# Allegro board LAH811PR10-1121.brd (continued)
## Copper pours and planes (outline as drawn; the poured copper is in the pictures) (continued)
PD_L_DRAIN2 on BOTTOM (solid shape): 32.01,35.22 32.01,35.03 31.97,34.99 30.85,34.99 30.75,34.88 30.75,33.78 30.85,33.68 31.97,33.68 32.02,33.63 32.02,33.44 31.96,33.37 28.5,33.37 28.36,33.23 28.36,32.16 28.31,32.11 28.16,32.11 28.08,32.18 28.08,33.28 28.16,33.36 28.16,35.12 30.68,35.12 30.82,35.27 31.96,35.27
PD_L_DRAIN2 on IN2 (solid shape): 30.75,35.1 30.75,33.37 28.16,33.37 28.16,35.12 30.73,35.12
PD_L_DRAIN2 on IN3 (solid shape): 30.75,33.37 28.16,33.37 28.16,35.12 30.75,35.12
PD_L_DRAIN2 on IN1: 28.16,33.37 28.16,35.12 30.75,35.12 30.75,33.37
PD_R_DRAIN1 on TOP (solid shape): 266.42,37.6 266.42,37.36 266.39,37.33 265.35,37.33 265.14,37.12 265.14,36.13 265.27,36 266.23,36 266.28,35.94 266.28,35.77 266.22,35.71 265.32,35.71 265.32,35.71 262.88,35.71 262.74,35.57 262.74,34.49 262.69,34.44 262.47,34.44 262.44,34.48 262.44,35.59 262.6,35.74 262.6,37.46 265.15,37.46 265.31,37.62 266.4,37.62
PD_R_DRAIN1 on BOTTOM (solid shape): 265.14,35.87 265.05,35.78 262.7,35.78 262.6,35.88 262.6,37.46 262.61,37.46 265.14,37.46
PD_R_DRAIN1 on IN1 (solid shape): 265.14,35.77 265.08,35.71 262.63,35.71 262.6,35.74 262.6,37.46 262.61,37.46 265.14,37.46
PD_R_DRAIN1 on IN2 (solid shape): 265.14,35.87 265.05,35.78 262.7,35.78 262.6,35.88 262.6,37.46 262.61,37.46 265.14,37.46
PD_R_DRAIN1 on IN3 (solid shape): 265.14,37.4 265.14,35.79 265.06,35.71 262.7,35.71 262.6,35.81 262.6,37.38 262.68,37.46 265.07,37.46
PD_R_DRAIN2 on TOP (solid shape): 259.69,37.46 262.24,37.46 262.24,35.68 262.32,35.6 262.32,34.5 262.24,34.42 262.1,34.42 262.04,34.48 262.04,35.58 261.91,35.71 259.59,35.71 259.58,35.69 258.45,35.69 258.38,35.76 258.38,35.95 258.43,36 259.48,36 259.54,36.06 259.54,37.26 259.5,37.31 258.44,37.31 258.4,37.35 258.4,37.53 258.45,37.58 259.56,37.58
PD_R_DRAIN2 on BOTTOM (solid shape): 262.24,35.89 262.13,35.78 260.5,35.78 260.5,36.24 259.66,36.24 259.66,37.46 262.24,37.46
PD_R_DRAIN2 on IN1 (solid shape): 262.24,35.76 262.19,35.71 259.78,35.71 259.65,35.84 259.65,37.46 259.66,37.46 262.24,37.46
PD_R_DRAIN2 on IN2 (solid shape): 262.24,35.89 262.13,35.78 259.78,35.78 259.66,35.91 259.66,37.46 262.24,37.46
PD_R_DRAIN2 on IN3 (solid shape): 262.24,37.44 262.24,35.81 262.14,35.71 260.38,35.71 260.38,36.05 259.66,36.77 259.66,37.42 259.7,37.46 262.22,37.46
RING2 on TOP (solid shape): 261.15,66.64 261.15,65.83 260.93,65.6 260.93,64.05 260.87,64 260.77,64 260.7,64.07 260.7,66.62 260.82,66.75 261.05,66.75
RING2 on BOTTOM (solid shape): 261.71,67.76 261.71,66.39 261,65.68 260.82,65.68 260.7,65.81 260.7,66.61 260.7,66.61 260.7,67.76 260.95,68.01 260.95,68.01 261.46,68.01
RING2 on IN3: 262.47,68.46 261.52,68.46 260.69,67.63 260.69,65.79 260.82,65.66 261.52,65.66 261.71,65.85 261.71,67.12 262.03,67.44 262.35,67.44 262.47,67.57
RING2 on IN3: 269.84,64.2 270.85,64.2 272.06,63 272.06,61.78 271.77,61.49 271.35,61.49 271.04,61.79 271.04,62.43 270.28,63.19 269.84,63.19
SLEEVE on TOP (solid shape): 260.54,67.39 260.54,64.08 260.47,64 260.36,64 260.29,64.07 260.29,65.6 260.04,65.86 260.04,67.38 260.1,67.44 260.49,67.44
SLEEVE on BOTTOM: 275.87,67.95 275.87,68.71 275.62,68.97 274.66,68.97 274.54,68.84 274.54,68.2 274.85,67.89 275.81,67.89
SLEEVE on IN2: 259.04,66.74 259.04,64.65 259.49,64.2 273.84,64.2 276.06,66.43 276.06,68.46 275.81,68.71 274.66,68.71 274.35,68.39 274.35,66.3 273.27,65.22 260.95,65.22 260.57,65.6 260.57,66.74 260.44,66.87 259.17,66.87
SLEEVE_CONN on BOTTOM: 274.55,67.75 274.73,67.57 276.61,67.57 276.65,67.53 276.65,67.2 276.38,66.93 276.38,65.82 276.11,65.55 272.2,65.55 272.12,65.63 272.12,67.56 272.31,67.75
SN_1.1V_MEM on BOTTOM (solid shape): 100.67,21.53 100.67,20.64 101.06,20.26 101.06,19.63 100.93,19.5 99.53,19.5 99.4,19.63 99.4,21.53 99.53,21.66 100.55,21.66
SN_3V on BOTTOM: 206.54,22.01 206.67,22.01 208.07,20.62 208.07,20.49 207.18,19.6 206.92,19.6 205.91,20.62 205.91,21.38
SNUB_CHG1 on BOTTOM (solid shape): 82.78,9.05 82.78,8.4 82.57,8.2 79.34,8.2 79.21,8.32 79.21,8.83 79.34,8.96 79.85,8.96 80.23,9.34 82.49,9.34
SNUB_CHG2 on BOTTOM (solid shape): 92.93,13.91 92.93,13.15 93.05,13.02 93.82,13.02 93.94,12.9 93.94,12.01 93.82,11.88 92.29,11.88 92.17,12.01 92.17,13.91 92.29,14.04 92.8,14.04
SPK_L+ on TOP: 19.65,29.15 19.65,30.27 17.41,32.5 17.41,32.68 17.57,32.83 20.66,32.83 20.92,32.58 20.92,30.17 23.43,27.65 23.43,27.09 23.33,26.99 21.81,26.99
SPK_L+ on BOTTOM: 17.21,32.07 17.08,32.2 17.08,32.71 17.21,32.83 19.75,32.83 19.88,32.71 19.88,32.2 19.75,32.07
SPK_L+_R on TOP (solid shape): 24.47,27.78 24.47,25.93 24.32,25.77 24.32,24.05 24.27,24 24.09,24 24.02,24.07 24.02,25.72 24,25.74 24,25.79 23.66,26.13 23.66,27.78 23.79,27.91 24.35,27.91
SPK_L- on TOP: 22.44,32.96 22.44,30.8 22.95,30.29 25.62,30.29 26.25,29.66 26.25,28.08 26.1,27.93 25.57,27.93 24.47,29.02 22.57,29.02 21.24,30.36 21.24,32.64 20.79,33.09 17.62,33.09 17.26,33.44 17.26,34.16 17.34,34.23 21.17,34.23
SPK_L- on BOTTOM: 17.21,33.09 17.08,33.22 17.08,33.98 17.21,34.1 18.1,34.1 18.48,33.72 19.75,33.72 19.88,33.6 19.88,33.22 19.75,33.09
SPK_L-_R on TOP (solid shape): 26.38,27.45 26.38,25.94 26.76,25.56 26.76,24.95 26.38,24.57 26.38,24.15 26.2,23.97 24.91,23.97 24.83,24.05 24.83,24.22 24.93,24.33 25.31,24.33 25.49,24.5 25.49,26.84 25.36,26.97 25.36,27.65 25.44,27.73 26.1,27.73
SPK_R+ on TOP: 265.77,29.66 265.77,29.28 265.9,29.15 267.81,29.15 267.93,29.28 267.93,30.17 267.92,30.18 267.92,30.69 267.73,30.88 267.11,30.88 266.99,30.77 266.99,30.37 266.42,29.79 266.29,29.79 266.28,29.79 265.9,29.79
SPK_R+ on BOTTOM: 271.24,33.6 271.36,33.47 271.36,32.71 271.24,32.58 268.06,32.58 267.93,32.71 267.93,33.47 268.06,33.6
SPK_R+ on IN3: 269.08,33.47 269.2,33.34 269.2,32.83 269.08,32.71 268.06,32.71 267.58,32.23 267.58,29.39 267.47,29.28 266.61,29.28 266.42,29.46 266.42,32.21 267.68,33.47
SPK_R+_R on TOP (solid shape): 269.2,31.69 270.6,31.69 270.68,31.61 270.68,31.46 270.61,31.39 268.85,31.39 268.77,31.31 268.06,31.31 267.92,31.18 267.06,31.18 266.93,31.31 266.93,31.83 267.04,31.95 268.95,31.95
SPK_R- on TOP: 269.84,39.06 269.97,38.93 270.22,38.93 270.35,38.8 270.35,38.07 270.2,37.92 268.9,37.92 268.82,38 268.82,39.95 268.85,39.97 268.85,40.13 269.12,40.4 269.7,40.4 269.84,40.26
SPK_R- on BOTTOM: 268.03,31.46 267.93,31.56 267.93,32.2 268.06,32.33 271.24,32.33 271.36,32.2 271.36,31.69 271.13,31.46
SPK_R- on IN3: 270.09,39.69 270.73,39.06 270.73,32.07 270.22,31.56 268.06,31.56 267.93,31.69 267.93,32.33 268.06,32.45 269.2,32.45 269.58,32.83 269.58,38.42 268.82,39.18 268.82,39.44 269.08,39.69
SPK_R-_R on TOP (solid shape): 270.19,37.51 270.19,35.93 270.41,35.72 270.41,34.17 270.85,33.73 270.85,32.21 270.82,32.17 270.6,32.17 270.52,32.25 270.52,32.91 269.76,33.67 269.76,35.07 269.18,35.65 269.18,35.93 268.92,36.19 268.92,37.38 269.03,37.48 269.03,37.49 269.13,37.59 270.12,37.59
N30252391 on BOTTOM (solid shape): 33.92,13.73 33.92,13.58 32.48,12.13 32.35,12.13 31.97,12.51 31.97,13.02 33.24,14.29 33.36,14.29
N30258320 on BOTTOM (solid shape): 39.72,7.48 39.72,6.86 39.57,6.71 37.41,6.71 37.35,6.77 37.35,7.32 37.41,7.38 38.2,7.38 38.46,7.64 39.55,7.64
N30277718 on TOP (solid shape): 39.71,3.5 39.71,1.59 39.59,1.47 37.17,1.47 37.05,1.59 37.05,3.5 37.17,3.62 39.59,3.62
N52032474 on TOP (solid shape): 202.21,63.87 202.21,63.75 201.39,62.92 201,62.92 200.38,63.55 200.38,63.82 201.19,64.64 201.45,64.64
N52032474 on BOTTOM (solid shape): 204.61,65.09 204.61,64.13 204.43,63.95 203.04,63.95 202.66,63.57 202.2,63.57 200.6,61.97 200.11,61.97 199.72,61.59 199.62,61.59 199.47,61.73 199.47,61.85 200.14,62.52 200.14,63.59 201.28,64.74 201.44,64.74 201.89,65.19 204.51,65.19
N52416800 on TOP: 33.24,2.38 31.59,2.38 31.43,2.23 31.43,1.53 31.51,1.45 33.26,1.45 33.3,1.49 33.3,2.32
N52752182 on BOTTOM (solid shape): 196.95,61.26 196.95,61.19 195.62,59.86 195.56,59.86 195.05,60.37 195.05,60.43 196.38,61.77 196.44,61.77
N52761358 on BOTTOM (solid shape): 189.49,68.59 189.8,68.59 190.25,68.14 190.25,68.01 189.68,67.44 189.55,67.44 188.53,68.46 188.53,68.52 188.98,68.97 189.1,68.97
N52765760 on BOTTOM (solid shape): 104.74,30.17 104.74,28.52 104.61,28.39 102.71,28.39 102.58,28.52 102.58,30.14 102.68,30.24 104.67,30.24
N52768296 on BOTTOM (solid shape): 103.72,39.5 103.72,38.55 103.91,38.36 104.87,38.36 104.93,38.3 104.93,37.66 104.87,37.6 102.71,37.6 102.58,37.72 102.58,39.5 102.64,39.57 103.66,39.57
N52924590 on TOP (solid shape): 203.54,49.98 203.54,48.07 203.29,47.82 202.02,47.82 201.89,47.95 201.89,49.34 202.66,50.11 203.42,50.11
N52924590 on BOTTOM (solid shape): 203.48,50.17 203.48,46.49 203.04,46.04 203.04,45.66 202.97,45.6 202.72,45.6 202.66,45.66 202.66,47.12 201.48,48.29 201.48,48.83 201.89,49.24 201.89,50.23 201.96,50.3 203.35,50.3
N52928923 on BOTTOM (solid shape): 192.5,52.65 192.5,50.93 192.43,50.87 191.54,50.87 191.48,50.93 191.48,51.38 190.97,51.88 190.97,52.65 191.03,52.71 192.43,52.71
N52929663 on TOP (solid shape): 204.94,42.11 204.94,41.72 204.81,41.6 202.91,41.6 202.78,41.72 202.78,42.11 202.91,42.23 204.81,42.23
N53177904 on BOTTOM (solid shape): 195.42,63.06 195.42,62.81 194.91,62.3 194.78,62.3 193.64,63.44 193.64,63.57 194.15,64.08 194.4,64.08
N53201443 on BOTTOM: 29.68,13.66 29.55,13.78 29.55,14.29 29.17,14.67 26.76,14.67 26.63,14.8 26.63,15.18 26.76,15.31 28.28,15.31 28.67,15.69 30.19,15.69 30.32,15.82 30.32,16.71 29.94,17.09 29.94,21.79 30.19,22.04 31.59,22.04 32.09,22.55 35.4,22.55 35.47,22.47 35.47,21.61 34.13,20.26 33.49,20.26 33.24,20.01 33.24,18.61 32.98,18.36 32.35,18.36 32.09,18.1 32.09,13.91 31.84,13.66
N53201576 on BOTTOM: 21.3,16.02 21.3,15.26 21.43,15.13 22.95,15.13 23.08,15.26 23.08,16.15 22.95,16.27 21.55,16.27
N53202040 on BOTTOM: 250.99,6.39 251.17,6.22 251.17,4.14 250.72,3.7 239.48,3.7 239.14,4.04 239.14,5.25 240.28,6.39
N53202040 on BOTTOM: 264.58,9.8 268.08,9.8 268.21,9.94 268.21,11.91 266.63,13.49 266.63,17.71 266.74,17.82 268,17.82 268.59,17.23 268.56,17.23 268.56,14.65 269.84,14.65 269.84,16.91 270.93,16.91 271.12,17.1 271.12,18.34 271.51,18.74 271.51,19.75 271.67,19.91 271.72,19.91 272.05,19.58 272.05,11.27 272.04,11.26 272.04,9.93 269.53,7.42 264.55,7.42 263.97,7.99 263.97,9.19
N53202040 on IN3: 250.2,5.07 250.2,5.96 250.43,6.19 250.56,6.19 250.56,6.6 250.96,7 253.28,7 253.81,7.54 261.06,7.54 261.65,6.94 261.65,6.67 261.83,6.49 262.69,6.49 262.98,6.77 262.98,7.89 263.46,8.37 265.22,8.37 265.46,8.12 265.46,5.52 264.14,4.19 264.14,3.55 263.88,3.29 259.91,3.29 258.78,4.43 250.85,4.43
N53202164 on BOTTOM: 273.77,25.65 274.47,25.65 274.59,25.52 274.59,24.07 274.5,23.98 273.74,23.98 273.65,24.07 273.65,25.52
N53202478 on TOP (solid shape): 273.22,19.96 273.22,19.07 273.09,18.94 270.8,18.94 270.68,19.07 270.68,19.96 270.8,20.08 273.09,20.08
N57581670 on BOTTOM (solid shape): 199.76,44.65 199.76,43.83 200.09,43.5 200.95,43.5 201,43.45 201,42.56 200.93,42.49 199.02,42.49 198.69,42.82 198.69,44.37 199.07,44.75 199.66,44.75
N58555592 on BOTTOM (solid shape): 109.77,69.88 109.77,69.62 109.54,69.39 109.54,69.39 109.45,69.39 109.45,68.83 109.47,68.83 109.47,68.79 109.55,68.72 109.88,68.72 109.95,68.65 109.95,68.39 109.82,68.27 109.44,68.27 109.37,68.2 109.37,67.84 109.34,67.8 109.34,67.72 109.18,67.56 108.42,67.56 108.26,67.72 108.26,69.33 108.5,69.57 108.86,69.57 108.89,69.6 108.98,69.6 109.18,69.79 109.18,69.84 109.32,69.98 109.67,69.98
N58555606 on BOTTOM (solid shape): 114.01,68.9 115.53,68.9 115.79,68.65 115.79,68.27 115.66,68.14 115.25,68.14 114.87,67.76 113.37,67.76 113.3,67.83 113.3,68.3 113.23,68.38 113.14,68.38 113.08,68.44 113.08,69.11 113.12,69.16 113.76,69.16
N73645370 on TOP (solid shape): 27.52,23.39 27.52,22.62 27.65,22.5 27.65,21.61 27.52,21.48 26.86,21.48 26.38,21.96 26.38,22.88 26.13,23.13 25.03,23.13 24.98,23.18 24.98,23.33 25.06,23.41 26.79,23.41 26.89,23.51 27.4,23.51
N73645628 on TOP (solid shape): 20.79,25.72 20.79,25.34 21.65,24.48 22.87,24.48 22.95,24.41 22.95,24.25 22.91,24.21 21.16,24.21 20.84,23.89 19.98,23.89 19.86,24.01 19.86,25.76 19.95,25.85 20.66,25.85
N73649539 on TOP (solid shape): 270.15,31.19 270.15,31.07 270.06,30.98 269.13,30.98 268.82,30.68 268.82,30.45 268.77,30.4 268.14,30.4 268.06,30.47 268.06,31.06 268.14,31.13 268.85,31.13 268.97,31.26 270.08,31.26
N73649541 on TOP (solid shape): 269.56,35.1 269.56,33.32 270.35,32.53 270.35,32.28 270.27,32.2 269.33,32.2 268.67,32.86 268.67,34.03 268.82,34.18 268.82,35.04 268.97,35.2 269.46,35.2
N73649585 on TOP (solid shape): 272.63,36.26 272.63,34.61 271.69,33.67 271.69,32.39 271.64,32.33 271.47,32.33 271.41,32.4 271.41,33.89 271.44,33.93 271.44,36.09 271.74,36.39 272.51,36.39
N77098291 on TOP: 210.1,1.16 210.81,1.16 210.88,1.24 210.88,2.2 210.67,2.42 210.39,2.42 210,2.03 210,1.26

Small or netless copper shapes (teardrops, artwork), in the pictures only: 22 on TOP, 51 on BOTTOM, 29 on IN1, 3 on IN2, 41 on IN3

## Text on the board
Ref Des/Silkscreen Bottom: H14 | S2 | H4 | HCPU2 | HCPU1 | H19 | H17 | HCPU4 | HCPU3 | H15 | H9 | S1 | H16 | HSSD1 | H18 | H20
User.Comments: LA-H811P | 2020-11-19 | 2019-11-19 | Minjia | FDQ30
Ref Des/Silkscreen Top: S3 | H6 | H7 | S4
GND4: GND4
User.45: 0_86mm_3+4+3(PTH L3_L8)(MidLoss)(TOP G-V IN1 G-V G-V IN2 G-V IN3 G-V BOT)_190102.pdf | 3.7 | 2.7 | 2.4 | 2 | 3.8/4.2 | 3.2/4.8 | 3/4.8 | 2.3/5.7 | 2.2/5.8 | Impedance | FIGURE | SIZE | 4.0 | DRILL CHART: GND1 to IN1 | ALL UNITS ARE IN MILS | DRILL CHART: GND1 to GND2 | DRILL CHART: TOP to GND1 | DRILL CHART: TOP to GND2 | TOLERANCE | +1.0/-1.0 | PLATED | QTY | 1766 | 1337 | 842 | 278 | 8.0 | DRILL CHART: GND4 to BOTTOM | DRILL CHART: IN1 to IN3 | DRILL CHART: TOP to IN1 | DRILL CHART: IN3 to GND4 | +3.0/-3.0 | 2082 | 2897 | 1603 | 51 | 529 | 63.0 | 102.0 | 130.0 | 142.0 | 24.0 | 40.0 | 43.0 | 51.0 | 39.0x20.0 | 43.0x20.0 | 49.0x26.0 | 63.0x22.0 | 67.0x22.0 | 71.0x16.0 | DRILL CHART: IN3 to BOTTOM | DRILL CHART: GND3 to IN3 | DRILL CHART: GND3 to BOTTOM | DRILL CHART: GND3 to GND4 | DRILL CHART: TOP to BOTTOM | +2.0/-2.0 | NON-PLATED | 1970 | 7 | 561 | 408 | 641 | 1680 | 35 | 1 | 5 | 6 | 4
